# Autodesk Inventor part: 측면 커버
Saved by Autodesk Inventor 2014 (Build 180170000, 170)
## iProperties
Created: 2026-05
Part Number: 측면 커버
Material: 일반
Document SubType Name: Modeling
Designer: dg
Density: 1 g/cm^3
Appearance: 기본값
Author: dg
Author: jhkim
Creation Date: 2026-04-23
Sending System: Autodesk Inventor 2027
Preprocessor: ST-DEVELOPER v20.1
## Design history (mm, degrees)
node "측면 커버1"
node "솔리드1"
node "기준1"
